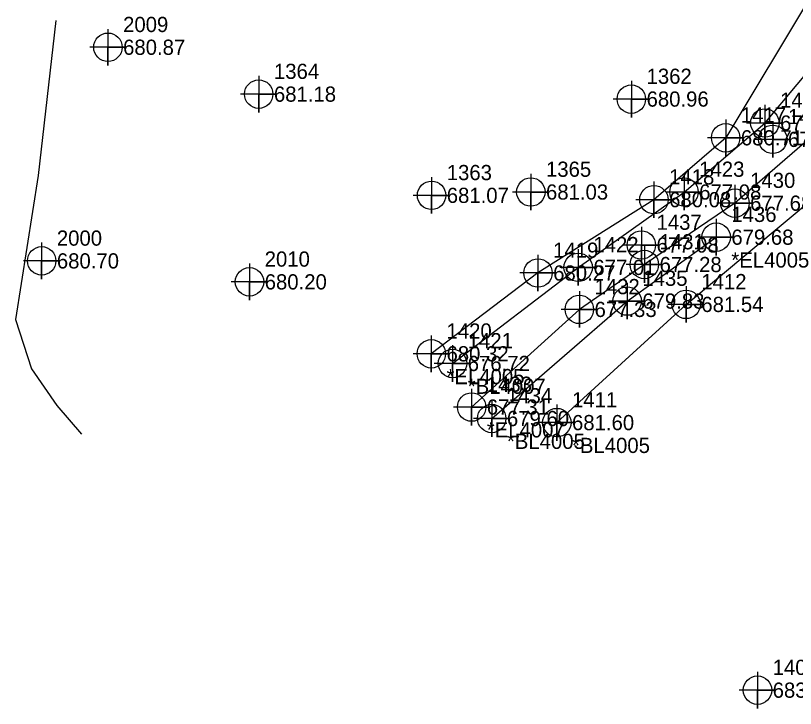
# Model space of a CAD drawing. Extents: x 1755643 to 1760494, y 736519 to 737621.
# Drawn here: x 1758923.1 to 1759051.4, y 736841.3 to 736955.3 of the extents above; entities that cross this region are included whole.
import ezdxf

# ---------------------------------------------------------------- set-up
doc = ezdxf.new("R2010")
doc.units = 0
for name, color, linetype in [('Exist Horizontal Alignment Curve and Spiral Data', 7, 'Continuous'), ('Exist Horizontal Alignment Direction Label', 7, 'Continuous'), ('Exist Railroads Standard Gauge', 7, 'Continuous'), ('Exist Roads EOT', 7, 'Continuous'), ('Exist Utilities Sanitary Sewer UG Line', 7, 'Continuous'), ('Old_Level_3', 7, 'Continuous'), ('Prop Conc 5in Monolithic Keyed In Island', 7, 'Continuous'), ('Prop EOT Dash', 7, 'Continuous'), ('Prop Horizontal Alignment Station Label', 7, 'Continuous'), ('Prop Horizontal Alignment Tick Label', 7, 'Continuous'), ('Prop Horizontal Alignment Tick Large', 7, 'Continuous'), ('Prop Horizontal Alignment Tick Small', 7, 'Continuous'), ('Prop Lane Lines', 7, 'Continuous'), ('Prop Paved Shoulder', 7, 'Continuous'), ('Prop Superelevation Label', 7, 'Continuous'), ('Prop Terminator CELL', 7, 'Continuous'), ('Scratch_Level_9', 7, 'Continuous')]:
    doc.layers.add(name, color=color, linetype=linetype)

msp = doc.modelspace()

# ---------------------------------------------------------------- linework, layer by layer
at = {"layer": 'Exist Horizontal Alignment Curve and Spiral Data'}
for points in [[(1758938.24, 736953.08), (1758938.24, 736947.08), (1758938.24, 736950.08), (1758941.24, 736950.08), (1758935.24, 736950.08)], [(1758963.06, 736945.37), (1758963.06, 736939.37), (1758963.06, 736942.37), (1758966.06, 736942.37), (1758960.06, 736942.37)], [(1759024.38, 736944.55), (1759024.38, 736938.55), (1759024.38, 736941.55), (1759027.38, 736941.55), (1759021.38, 736941.55)], [(1758991.5, 736928.72), (1758991.5, 736922.72), (1758991.5, 736925.72), (1758994.5, 736925.72), (1758988.5, 736925.72)], [(1759007.83, 736929.27), (1759007.83, 736923.27), (1759007.83, 736926.27), (1759010.83, 736926.27), (1759004.83, 736926.27)], [(1758927.34, 736917.94), (1758927.34, 736911.94), (1758927.34, 736914.94), (1758930.34, 736914.94), (1758924.34, 736914.94)], [(1758961.54, 736914.49), (1758961.54, 736908.49), (1758961.54, 736911.49), (1758964.54, 736911.49), (1758958.54, 736911.49)], [(1759045.13, 736847.33), (1759045.13, 736841.33), (1759045.13, 736844.33), (1759048.13, 736844.33), (1759042.13, 736844.33)]]:
    msp.add_lwpolyline(points, dxfattribs=at)
for centre in [(1758938.24, 736950.08), (1758963.06, 736942.37), (1759024.38, 736941.55), (1759007.83, 736926.27), (1758991.5, 736925.72), (1758927.34, 736914.94), (1758961.54, 736911.49), (1759045.13, 736844.33)]:
    msp.add_circle(centre, 2.34, dxfattribs=at)
at = {"layer": 'Exist Railroads Standard Gauge'}
msp.add_lwpolyline([(1758929.66, 736954.46), (1758926.79, 736929.01), (1758923.05, 736905.3), (1758925.69, 736897.21), (1758929.82, 736891.16), (1758933.91, 736886.45)], dxfattribs=at)
at = {"layer": 'Prop Horizontal Alignment Station Label'}
for points in [[(1759047.65, 736937.93), (1759047.65, 736931.93), (1759047.65, 736934.93), (1759050.65, 736934.93), (1759044.65, 736934.93)], [(1759026.02, 736920.55), (1759026.02, 736914.55), (1759026.02, 736917.55), (1759029.02, 736917.55), (1759023.02, 736917.55)]]:
    msp.add_lwpolyline(points, dxfattribs=at)
for centre in [(1759047.65, 736934.93), (1759026.02, 736917.55)]:
    msp.add_circle(centre, 2.34, dxfattribs=at)
at = {"layer": 'Prop Horizontal Alignment Tick Small'}
for points in [[(1759046.35, 736940.62), (1759046.35, 736934.62), (1759046.35, 736937.62), (1759049.35, 736937.62), (1759043.35, 736937.62)], [(1759033.04, 736929.27), (1759033.04, 736923.27), (1759033.04, 736926.27), (1759036.04, 736926.27), (1759030.04, 736926.27)], [(1759041.42, 736927.44), (1759041.42, 736921.44), (1759041.42, 736924.44), (1759044.42, 736924.44), (1759038.42, 736924.44)], [(1759026.52, 736917.34), (1759026.52, 736911.34), (1759026.52, 736914.34), (1759029.52, 736914.34), (1759023.52, 736914.34)], [(1759015.63, 736916.87), (1759015.63, 736910.87), (1759015.63, 736913.87), (1759018.63, 736913.87), (1759012.63, 736913.87)], [(1759015.82, 736909.96), (1759015.82, 736903.96), (1759015.82, 736906.96), (1759018.82, 736906.96), (1759012.82, 736906.96)], [(1758994.95, 736901.07), (1758994.95, 736895.07), (1758994.95, 736898.07), (1758997.95, 736898.07), (1758991.95, 736898.07)], [(1758998.09, 736893.89), (1758998.09, 736887.89), (1758998.09, 736890.89), (1759001.09, 736890.89), (1758995.09, 736890.89)]]:
    msp.add_lwpolyline(points, dxfattribs=at)
for centre in [(1759046.35, 736937.62), (1759033.04, 736926.27), (1759041.42, 736924.44), (1759015.63, 736913.87), (1759026.52, 736914.34), (1759015.82, 736906.96), (1758994.95, 736898.07), (1758998.09, 736890.89)]:
    msp.add_circle(centre, 2.34, dxfattribs=at)
at = {"layer": 'Prop Lane Lines'}
for points in [[(1759039.9, 736938.19), (1759039.9, 736932.19), (1759039.9, 736935.19), (1759042.9, 736935.19), (1759036.9, 736935.19)], [(1759028.09, 736928), (1759028.09, 736922), (1759028.09, 736925), (1759031.09, 736925), (1759025.09, 736925)], [(1759038.33, 736921.84), (1759038.33, 736915.84), (1759038.33, 736918.84), (1759041.33, 736918.84), (1759035.33, 736918.84)], [(1759009.01, 736915.95), (1759009.01, 736909.95), (1759009.01, 736912.95), (1759012.01, 736912.95), (1759006.01, 736912.95)], [(1759023.68, 736911.33), (1759023.68, 736905.33), (1759023.68, 736908.33), (1759026.68, 736908.33), (1759020.68, 736908.33)], [(1759033.39, 736910.78), (1759033.39, 736904.78), (1759033.39, 736907.78), (1759036.39, 736907.78), (1759030.39, 736907.78)], [(1758991.46, 736902.66), (1758991.46, 736896.66), (1758991.46, 736899.66), (1758994.46, 736899.66), (1758988.46, 736899.66)], [(1759001.4, 736892.01), (1759001.4, 736886.01), (1759001.4, 736889.01), (1759004.4, 736889.01), (1758998.4, 736889.01)], [(1759012.11, 736891.34), (1759012.11, 736885.34), (1759012.11, 736888.34), (1759015.11, 736888.34), (1759009.11, 736888.34)]]:
    msp.add_lwpolyline(points, dxfattribs=at)
for centre in [(1759039.9, 736935.19), (1759028.09, 736925), (1759038.33, 736918.84), (1759009.01, 736912.95), (1759023.68, 736908.33), (1759033.39, 736907.78), (1758991.46, 736899.66), (1759001.4, 736889.01), (1759012.11, 736888.34)]:
    msp.add_circle(centre, 2.34, dxfattribs=at)
at = {"layer": 'Prop Terminator CELL'}
for points in [[(1759085.36, 736977.22), (1759077.71, 736962.26), (1759059.08, 736939.73), (1759041.42, 736924.44), (1759026.52, 736914.34), (1759015.82, 736906.96), (1758998.09, 736890.89)], [(1758994.95, 736898.07), (1759015.63, 736913.87), (1759033.04, 736926.27), (1759046.35, 736937.62), (1759056.99, 736950.3), (1759075.76, 736966.95), (1759081.56, 736973.31)]]:
    msp.add_lwpolyline(points, dxfattribs=at)
at = {"layer": 'Scratch_Level_9'}
for points in [[(1759012.11, 736888.34), (1759033.39, 736907.78), (1759054.66, 736925.52), (1759072.98, 736940.45), (1759084.33, 736957.28), (1759108.25, 736984.06)], [(1759076.94, 736972), (1759053.84, 736958.45), (1759039.9, 736935.19), (1759028.09, 736925), (1759009.01, 736912.95), (1758991.46, 736899.66)], [(1759001.4, 736889.01), (1759023.68, 736908.33), (1759038.33, 736918.84)]]:
    msp.add_lwpolyline(points, dxfattribs=at)

# ---------------------------------------------------------------- texts
at = {"layer": 'Exist Horizontal Alignment Direction Label'}
for s, p in [('*EL4005', (1759040.83, 736913.84)), ('*EL4005', (1758993.96, 736894.66)), ('*BL4005', (1759003.9, 736884.01)), ('*BL4005', (1759014.61, 736883.34))]:
    msp.add_text(s, height=2.5, dxfattribs=at).set_placement(p)
at = {"layer": 'Exist Roads EOT'}
for s, p in [('2009', (1758940.74, 736952.58)), ('1364', (1758965.56, 736944.87)), ('1362', (1759026.88, 736944.06)), ('1365', (1759010.33, 736928.77)), ('1363', (1758994, 736928.22)), ('2000', (1758929.84, 736917.44)), ('2010', (1758964.04, 736913.99)), ('1408', (1759047.63, 736846.83))]:
    msp.add_text(s, height=2.5, dxfattribs=at).set_placement(p)
at = {"layer": 'Exist Utilities Sanitary Sewer UG Line'}
for s, p in [('677.33', (1759048.85, 736936.37)), ('677.08', (1759035.54, 736925.02)), ('677.68', (1759043.92, 736923.19)), ('677.01', (1759018.13, 736912.62)), ('677.28', (1759029.02, 736913.09)), ('677.33', (1759018.32, 736905.71)), ('676.72', (1758997.45, 736896.82)), ('677.31', (1759000.59, 736889.65))]:
    msp.add_text(s, height=2.5, dxfattribs=at).set_placement(p)
at = {"layer": 'Old_Level_3'}
for s, p in [('680.71', (1759042.4, 736933.94)), ('680.08', (1759030.59, 736923.76)), ('679.68', (1759040.83, 736917.59)), ('680.27', (1759011.51, 736911.7)), ('679.83', (1759026.18, 736907.08)), ('681.54', (1759035.89, 736906.53)), ('680.32', (1758993.96, 736898.41)), ('679.60', (1759003.9, 736887.76)), ('681.60', (1759014.61, 736887.09))]:
    msp.add_text(s, height=2.5, dxfattribs=at).set_placement(p)
at = {"layer": 'Prop Conc 5in Monolithic Keyed In Island'}
for s, p in [('1424', (1759048.85, 736940.12)), ('1423', (1759035.54, 736928.77)), ('1430', (1759043.92, 736926.94)), ('1422', (1759018.13, 736916.37)), ('1431', (1759029.02, 736916.84)), ('1432', (1759018.32, 736909.46)), ('1421', (1758997.45, 736900.57)), ('1433', (1759000.59, 736893.4))]:
    msp.add_text(s, height=2.5, dxfattribs=at).set_placement(p)
at = {"layer": 'Prop EOT Dash'}
for s, p in [('1417', (1759042.4, 736937.69)), ('1418', (1759030.59, 736927.51)), ('1436', (1759040.83, 736921.34)), ('1419', (1759011.51, 736915.45)), ('1435', (1759026.18, 736910.83)), ('1412', (1759035.89, 736910.28)), ('1420', (1758993.96, 736902.16)), ('1434', (1759003.9, 736891.51)), ('1411', (1759014.61, 736890.84))]:
    msp.add_text(s, height=2.5, dxfattribs=at).set_placement(p)
at = {"layer": 'Prop Horizontal Alignment Tick Label'}
for s, p in [('1438', (1759050.15, 736937.43)), ('1437', (1759028.52, 736920.05))]:
    msp.add_text(s, height=2.5, dxfattribs=at).set_placement(p)
at = {"layer": 'Prop Horizontal Alignment Tick Large'}
for s, p in [('677.13', (1759050.15, 736933.68)), ('677.08', (1759028.52, 736916.3))]:
    msp.add_text(s, height=2.5, dxfattribs=at).set_placement(p)
at = {"layer": 'Prop Paved Shoulder'}
for s, p in [('680.87', (1758940.74, 736948.83)), ('681.18', (1758965.56, 736941.12)), ('680.96', (1759026.88, 736940.31)), ('681.03', (1759010.33, 736925.02)), ('681.07', (1758994, 736924.47)), ('680.70', (1758929.84, 736913.69)), ('680.20', (1758964.04, 736910.24)), ('683.66', (1759047.63, 736843.08))]:
    msp.add_text(s, height=2.5, dxfattribs=at).set_placement(p)
at = {"layer": 'Prop Superelevation Label'}
for s, p in [('*BL4007', (1758997.45, 736893.07)), ('*EL4007', (1759000.59, 736885.9))]:
    msp.add_text(s, height=2.5, dxfattribs=at).set_placement(p)

doc.saveas('drawing.dxf')
